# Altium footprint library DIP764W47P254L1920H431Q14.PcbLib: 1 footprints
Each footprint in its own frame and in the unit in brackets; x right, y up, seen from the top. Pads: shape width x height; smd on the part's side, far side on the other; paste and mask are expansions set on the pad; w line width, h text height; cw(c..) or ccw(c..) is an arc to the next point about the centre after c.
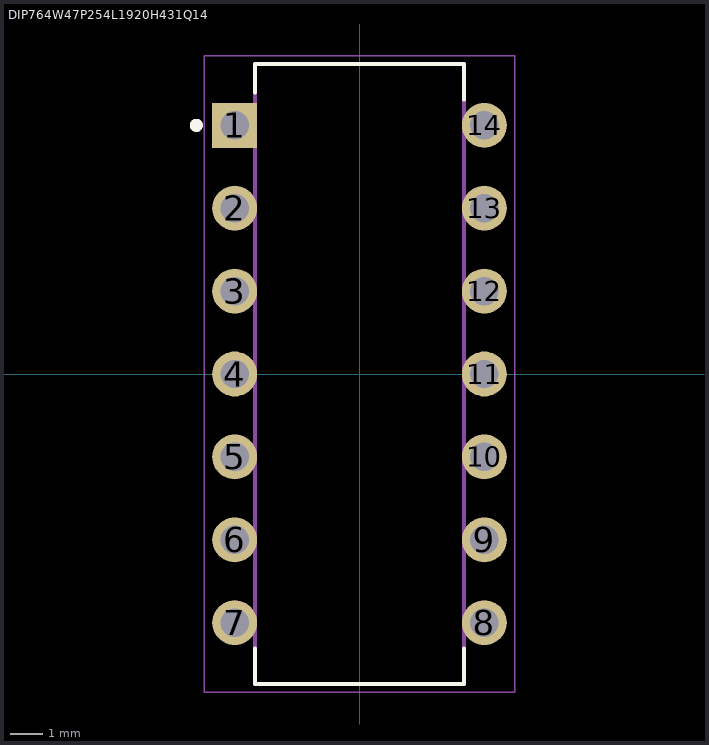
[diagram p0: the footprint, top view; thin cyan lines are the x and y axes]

## DIP764W47P254L1920H431Q14 [mm]
height 4.31
pads (14):
  rect 1.378x1.378 / inner round 1.378 / far side rect 1.378x1.378 hole 0.87 mask+0.102: 1(-3.824,7.62)
  round 1.378 hole 0.87 mask+0.102: 2(-3.824,5.08) 3(-3.824,2.54) 4(-3.824,0) 5(-3.824,-2.54) 6(-3.824,-5.08) 7(-3.824,-7.62) 8(3.824,-7.62) 9(3.824,-5.08) 10(3.824,-2.54) 11(3.824,0) 12(3.824,2.54) 13(3.824,5.08) 14(3.824,7.62)
Top Overlay:
  circle w0.2: c-5,7.62 r0.1
  lines w0.127: -3.2,-8.41 -3.2,-9.5 3.2,-9.5 3.2,-8.41 ; -3.2,8.624 -3.2,9.5 3.2,9.5 3.2,8.41
Assembly Top:
  circle w0.2: c-5,7.62 r0.1
  lines w0.127: -3.2,-9.5 3.2,-9.5 3.2,9.5 -3.2,9.5 -3.2,-9.5
Courtyard Top:
  lines w0.05: -4.763,-9.75 4.763,-9.75 4.763,9.75 -4.763,9.75 -4.763,-9.75
3D body "step_temp.STEP": height 4.31, standoff -3.6, extent -3.965,-9.5 3.965,9.5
